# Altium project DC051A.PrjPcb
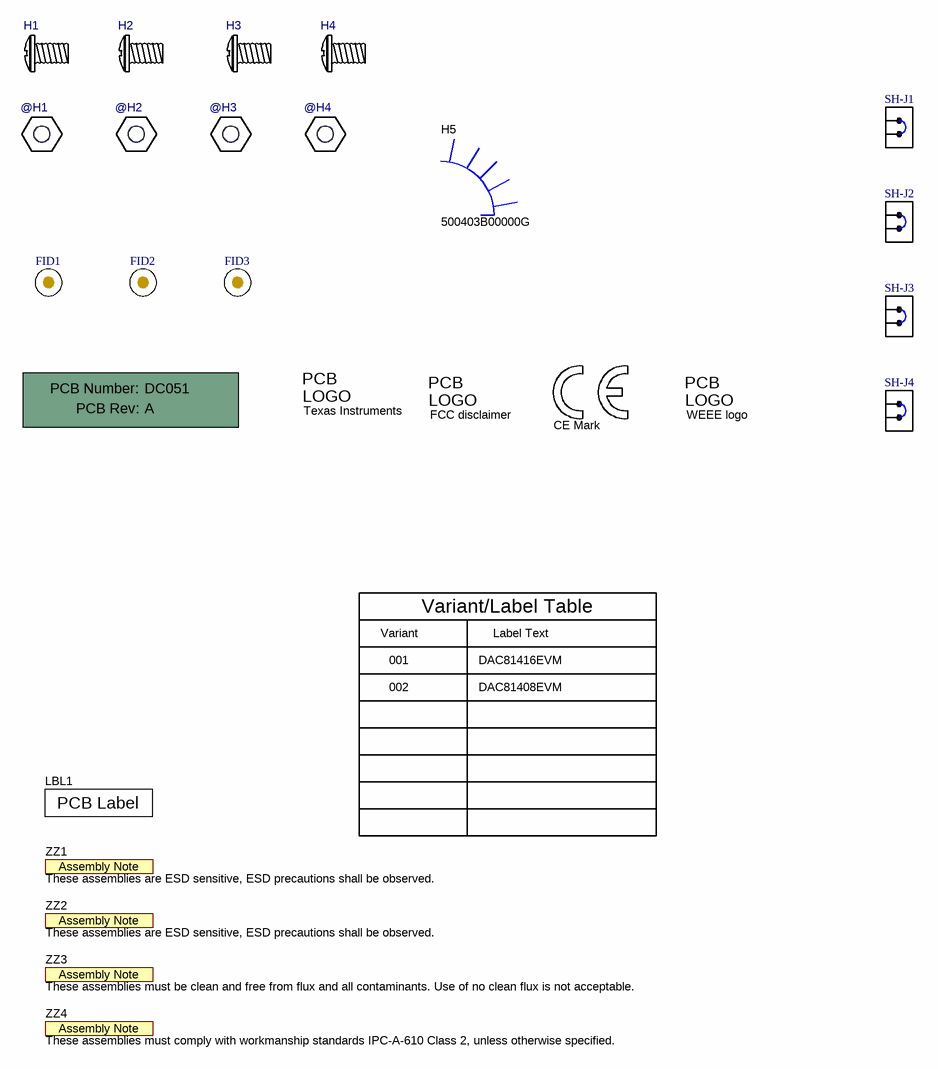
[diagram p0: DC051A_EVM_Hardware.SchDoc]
CopyrightYear: 2018; PCB_Layout: VENU; PCB_Rev: A; PRJ_Customer: Public Release; PRJ_Engineer: Uttama Kumar Sahu; PRJ_Number: DC051; PRJ_Title: DAC814xx EVM; SCH_Rev: A; TechSupport: http://www.ti.com/support; TID: N/A
2 sheets, 96 parts. Net scope: flat (ports and power ports of the same name join across sheets).
Board file: DC051A.PcbDoc
Sheets:
  DC051A_EVM_Hardware.SchDoc
  DC051A.SchDoc

## Sheet DC051A_EVM_Hardware.SchDoc
size 431 x 279 mm; Date: Not shown in title block; ApprovedBy: Not shown in title block; CheckedBy: Not shown in title block; Author: Not shown in title block; CompanyName: Not shown in title block; Engineer: Not shown in title block; Organization: Not shown in title block; Address1: Not shown in title block; Address2: Not shown in title block; Address3: Not shown in title block; Address4: Not shown in title block; DocumentNumber: 1; Revision: Use project parameter SCH_Rev; SheetNumber: 1; SheetTotal: 2; PageSetup: Record=PageOptions¦CenterHorizontal=True¦CenterVertical=True¦PrintScale=1.00¦XCorrection=1.00¦YCorrection=1.00¦PrintKind=0¦BorderSize=5000000¦LeftOffset=0¦BottomOffset=0¦Orientation=2¦PaperLength=1000¦PaperWidth=1000¦Scale=100¦PaperSource=15¦PrintQuality=600¦MediaType=1¦DitherType=10¦PaperKind=Letter¦PrintScaleMode=1

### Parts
!PCB  Printed Circuit Board  (value not drawn)  (mechanical)
@H1  1891  [Keystone_1891]  (value not drawn)
@H2  1891  [Keystone_1891]  (value not drawn)
@H3  1891  [Keystone_1891]  (value not drawn)
@H4  1891  [Keystone_1891]  (value not drawn)
FID1  Fiducial  [Fiducial10-30]  (value not drawn)
FID2  Fiducial  [Fiducial10-30]  (value not drawn)
FID3  Fiducial  [Fiducial10-30]  (value not drawn)
H1  29311  [Keystone29311]  (value not drawn)
H2  29311  [Keystone29311]  (value not drawn)
H3  29311  [Keystone29311]  (value not drawn)
H4  29311  [Keystone29311]  (value not drawn)
H5  500403B00000G  [Aavid_500403B00000G]
LBL1  THT-14-423-10  [Label_650x200]  (value not drawn)
Logo1  Texas Instruments  [TI_Stacked_Overlay_Medium]  (no BOM)
Logo2  FCC disclaimer  [FCC_disclaimer]  (no BOM)
Logo3  WEEE logo  [WEEE_Minimum]  (no BOM)
LOGO4  CE Mark  [CE_Mark_5mm]  (no BOM)
SH-J1  SNT-100-BK-G  [SNT-100-BK-G]  (value not drawn)
SH-J2  SNT-100-BK-G  [SNT-100-BK-G]  (value not drawn)
SH-J3  SNT-100-BK-G  [SNT-100-BK-G]  (value not drawn)
SH-J4  SNT-100-BK-G  [SNT-100-BK-G]  (value not drawn)
ZZ1  These assemblies are ESD sensitive, ESD precautions shall be observed.  [AssemblyNote]  (no BOM)
ZZ2  These assemblies are ESD sensitive, ESD precautions shall be observed.  [AssemblyNote]  (no BOM)
ZZ3  These assemblies must be clean and free from flux and all contaminants. Use of no clean flux is not acceptable.  [AssemblyNote]  (no BOM)
ZZ4  These assemblies must comply with workmanship standards IPC-A-610 Class 2, unless otherwise specified.  [AssemblyNote]  (no BOM)

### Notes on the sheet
- Variant
- Variant/Label Table
- Label Text
- 001
- 002
- DAC81416EVM
- DAC81408EVM

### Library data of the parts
!PCB = CMP-0003618-2: PartNumber: DC051; Manufacturer: Any
@H1-@H4 = CMP-0003792-1: Hex Standoff, #4-40, Aluminum, 1/4"; Manufacturer: Keystone
FID1-FID3 = CMP-0077181-1: Fiducial mark.  There is nothing to buy or mount.
H1-H4 = CMP-0003639-1: Screw Pan Head M3; Manufacturer: Keystone; CompType: Hardware
H5 = 500403B00000G: Square Basket Heatsink Featuring Slanted Fins; Manufacturer: Aavid; SymbolCreator: a0412235
LBL1 = CMP-0003625-1: Thermal Transfer Printable Labels, 0.650" W x 0.200" H - 10,000 per roll; Manufacturer: Brady; Note: Size: 0.65" x 0.20 "
Logo1 = CMP-0074838-1: Texas Instrument Corporate Signature; Library Reference: Logo; SymbolCreator: a0412235; Lib Reference: TI_Logo
Logo2 = CMP-0074847-1: FCC_disclaimer
Logo3 = CMP-0074769-1
LOGO4 = CMP-0074844-1: SymbolCreator: a0412235
SH-J1-SH-J4 = CMP-0003623-1: Shunt, 100mil, Gold plated, Black; Alternate PartNumber: 969102-0000-DA; Manufacturer: Samtec; Alternate Manufacturer: 3M; Value: 1x2; Note: You can "mate" this to a header by matching the designator.  i.e. use SH-J3 for header J3
ZZ1 = CMP-0003615-1: Install label in silkscreened box after final wash.  Text shall be 8 pt font.  Text shall be per the Label Table in the PDF schematic.
ZZ2-ZZ4 = CMP-0003615-1

## Sheet DC051A.SchDoc
size 431 x 279 mm; Date: Not shown in title block; ApprovedBy: Not shown in title block; CheckedBy: Not shown in title block; Author: Not shown in title block; CompanyName: Not shown in title block; Engineer: Not shown in title block; Organization: Not shown in title block; Address1: Not shown in title block; Address2: Not shown in title block; Address3: Not shown in title block; Address4: Not shown in title block; DocumentNumber: 2; Revision: Use project parameter SCH_Rev; SheetNumber: 2; SheetTotal: 2; PageSetup: Record=PageOptions¦CenterHorizontal=True¦CenterVertical=True¦PrintScale=0.62¦XCorrection=1.00¦YCorrection=1.00¦PrintKind=0¦BorderSize=5000000¦LeftOffset=0¦BottomOffset=0¦Orientation=2¦PaperLength=1000¦PaperWidth=1000¦Scale=100¦PaperSource=15¦PrintQuality=600¦MediaType=1¦DitherType=10¦PrintScaleMode=1¦PaperKind=Letter
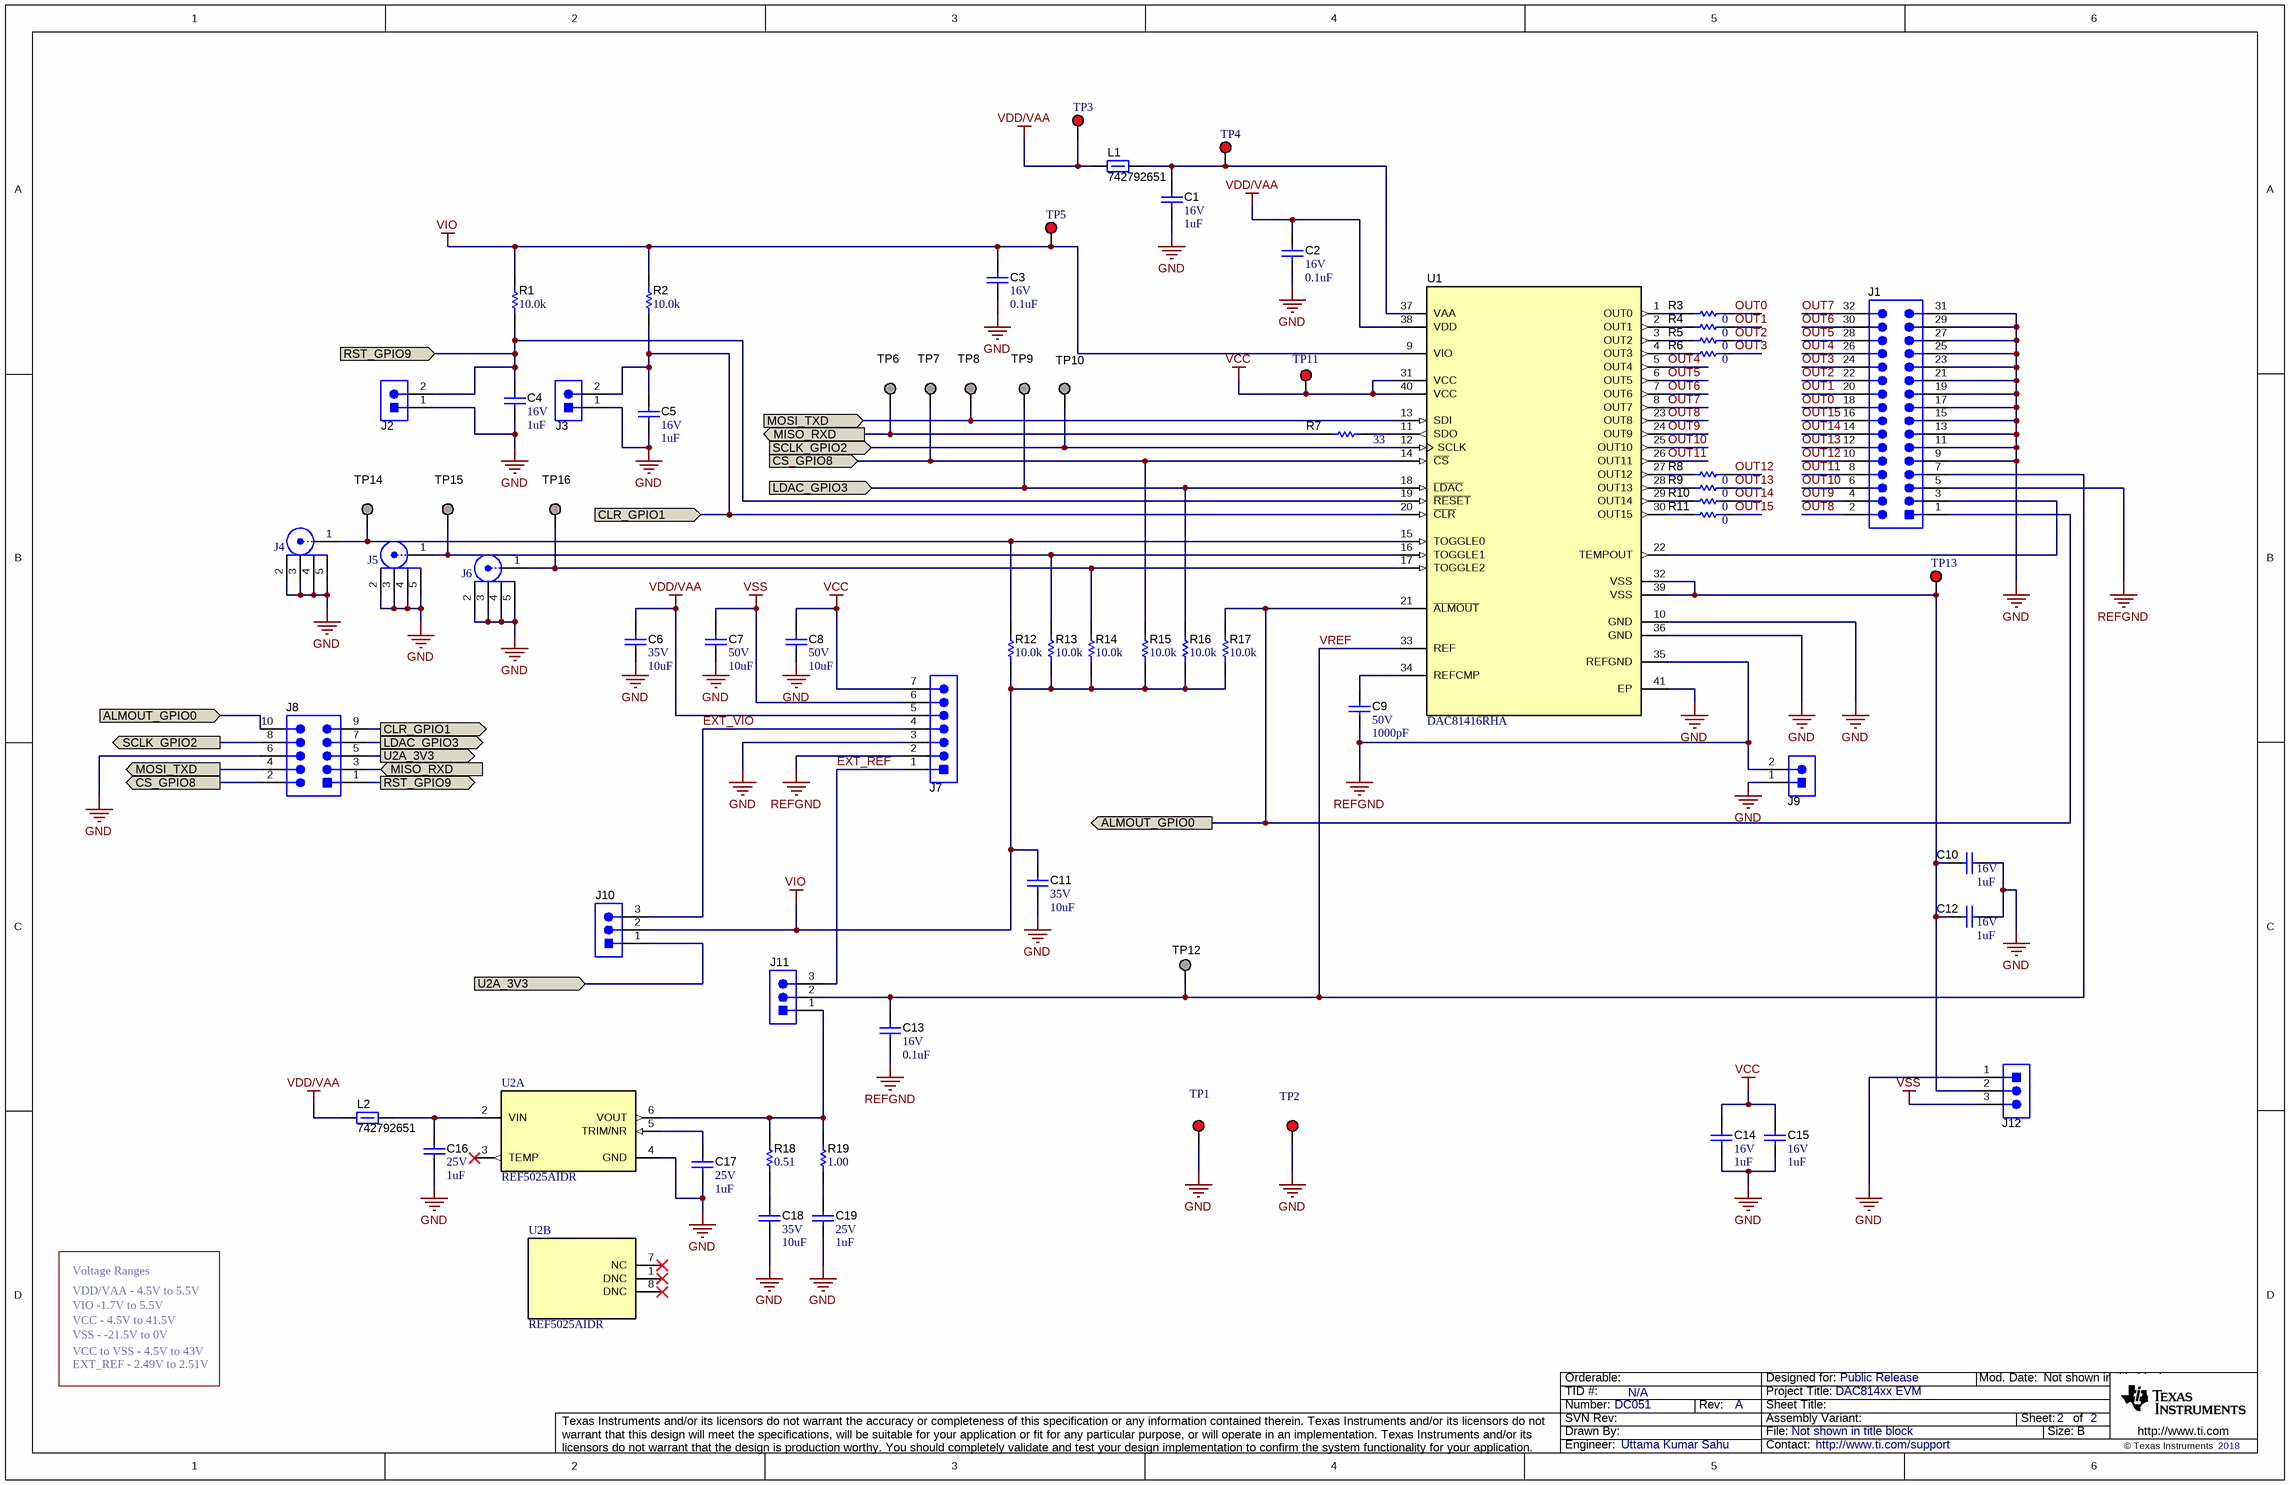
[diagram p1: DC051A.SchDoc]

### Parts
C1  VDC_V: 16V  ValueDisplayed: 1uF  [0603]  (hidden comment: C0603C105K4PACTU)
C2  VDC_V: 16V  ValueDisplayed: 0.1uF  [0603]  (hidden comment: C0603C104J4RACTU)
C3  VDC_V: 16V  ValueDisplayed: 0.1uF  [0603]  (hidden comment: C0603C104J4RACTU)
C4  VDC_V: 16V  ValueDisplayed: 1uF  [0603]  (hidden comment: C0603C105K4PACTU)
C5  VDC_V: 16V  ValueDisplayed: 1uF  [0603]  (hidden comment: C0603C105K4PACTU)
C6  VDC_V: 35V  ValueDisplayed: 10uF  [0805_HV]  (hidden comment: GRM21BC8YA106KE11L)
C7  VDC_V: 50V  ValueDisplayed: 10uF  [1210_270]  (hidden comment: UMJ325KB7106KMHT)
C8  VDC_V: 50V  ValueDisplayed: 10uF  [1210_270]  (hidden comment: UMJ325KB7106KMHT)
C9  VDC_V: 50V  ValueDisplayed: 1000pF  [0603]  (hidden comment: C0603C102K5RACTU)
C10  VDC_V: 16V  ValueDisplayed: 1uF  [0603]  (hidden comment: C0603C105K4PACTU)
C11  VDC_V: 35V  ValueDisplayed: 10uF  [0805_HV]  (hidden comment: GRM21BC8YA106KE11L)
C12  VDC_V: 16V  ValueDisplayed: 1uF  [0603]  (hidden comment: C0603C105K4PACTU)
C13  VDC_V: 16V  ValueDisplayed: 0.1uF  [0603]  (hidden comment: C0603C104J4RACTU)
C14  VDC_V: 16V  ValueDisplayed: 1uF  [0603]  (hidden comment: C0603C105K4PACTU)
C15  VDC_V: 16V  ValueDisplayed: 1uF  [0603]  (hidden comment: C0603C105K4PACTU)
C16  VDC_V: 25V  ValueDisplayed: 1uF  [0603]  (hidden comment: C1608X5R1E105K080AC)
C17  VDC_V: 25V  ValueDisplayed: 1uF  [0603]  (hidden comment: C1608X5R1E105K080AC)
C18  VDC_V: 35V  ValueDisplayed: 10uF  [0805_HV]  (hidden comment: GRM21BC8YA106KE11L)
C19  VDC_V: 25V  ValueDisplayed: 1uF  [0603]  (hidden comment: C1608X5R1E105K080AC)
J1  TSM-116-01-T-DV-P  [CONN_TSM-116-01-T-DV-P]  (value not drawn)
J2  TSM-102-01-L-SV  [Samtec_TSM-102-01-L-SV]  (value not drawn)
J3  TSM-102-01-L-SV  [Samtec_TSM-102-01-L-SV]  (value not drawn)
J4  142-0701-231  [Johnson_142-0701-231]  (value not drawn)
J5  142-0701-231  [Johnson_142-0701-231]  (value not drawn)
J6  142-0701-231  [Johnson_142-0701-231]  (value not drawn)
J7  1984662  [Phoenix_1984662]  (value not drawn)
J8  AWHW-10G-0202-T  [Assman_AWHW-10G-0x02-T]  (value not drawn)
J9  TSM-102-01-L-SV  [Samtec_TSM-102-01-L-SV]  (value not drawn)
J10  TSM-103-01-L-SV-P-TR  [Samtec_TSM-103-01-x-SV-P]  (value not drawn)
J11  TSM-103-01-L-SV-P-TR  [Samtec_TSM-103-01-x-SV-P]  (value not drawn)
J12  TSM-103-01-L-SV-P-TR  [Samtec_TSM-103-01-x-SV-P]  (value not drawn)
L1  742792651  [0603]
L2  742792651  [0603]
R1  ValueDisplayed: 10.0k  [0603]  (hidden comment: RC0603FR-0710KL)
R2  ValueDisplayed: 10.0k  [0603]  (hidden comment: RC0603FR-0710KL)
R3  ValueDisplayed: 0  [0603]  (hidden comment: RC0603JR-070RL)
R4  ValueDisplayed: 0  [0603]  (hidden comment: RC0603JR-070RL)
R5  ValueDisplayed: 0  [0603]  (hidden comment: RC0603JR-070RL)
R6  ValueDisplayed: 0  [0603]  (hidden comment: RC0603JR-070RL)
R7  ValueDisplayed: 33  [0603]  (hidden comment: CRCW060333R0JNEA)
R8  ValueDisplayed: 0  [0603]  (hidden comment: RC0603JR-070RL)
R9  ValueDisplayed: 0  [0603]  (hidden comment: RC0603JR-070RL)
R10  ValueDisplayed: 0  [0603]  (hidden comment: RC0603JR-070RL)
R11  ValueDisplayed: 0  [0603]  (hidden comment: RC0603JR-070RL)
R12  ValueDisplayed: 10.0k  [0603]  (hidden comment: RC0603FR-0710KL)
R13  ValueDisplayed: 10.0k  [0603]  (hidden comment: RC0603FR-0710KL)
R14  ValueDisplayed: 10.0k  [0603]  (hidden comment: RC0603FR-0710KL)
R15  ValueDisplayed: 10.0k  [0603]  (hidden comment: RC0603FR-0710KL)
R16  ValueDisplayed: 10.0k  [0603]  (hidden comment: RC0603FR-0710KL)
R17  ValueDisplayed: 10.0k  [0603]  (hidden comment: RC0603FR-0710KL)
R18  ValueDisplayed: 0.51  [0603]  (hidden comment: ERJ-3RQFR51V)
R19  ValueDisplayed: 1.00  [0603]  (hidden comment: RC0603FR-071RL)
TP1  5005  [Keystone5005]  (value not drawn)
TP2  5005  [Keystone5005]  (value not drawn)
TP3  5005  [Keystone5005]  (value not drawn)
TP4  5005  [Keystone5005]  (value not drawn)
TP5  5005  [Keystone5005]  (value not drawn)
TP6  5019  [Keystone_5019]  (value not drawn)
TP7  5019  [Keystone_5019]  (value not drawn)
TP8  5019  [Keystone_5019]  (value not drawn)
TP9  5019  [Keystone_5019]  (value not drawn)
TP10  5019  [Keystone_5019]  (value not drawn)
TP11  5005  [Keystone5005]  (value not drawn)
TP12  TP_SM_1MM  [TP_SM_1MM]  (value not drawn)  (no BOM)
TP13  5005  [Keystone5005]  (value not drawn)
TP14  5019  [Keystone_5019]  (value not drawn)
TP15  5019  [Keystone_5019]  (value not drawn)
TP16  5019  [Keystone_5019]  (value not drawn)
U1  DAC81416RHA  [RHA0040H]
U2  REF5025AIDR  [D0008A_N]  (parts A,B of 2)

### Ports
ALMOUT_GPIO0 (in), ALMOUT_GPIO0 (out), CLR_GPIO1 (in), CLR_GPIO1 (out), CS_GPIO8 (in), CS_GPIO8 (out), LDAC_GPIO3 (in), LDAC_GPIO3 (out), MISO_RXD (in), MISO_RXD (out), MOSI_TXD (in), MOSI_TXD (out), RST_GPIO9 (in), RST_GPIO9 (out), SCLK_GPIO2 (in), SCLK_GPIO2 (out), U2A_3V3 (in), U2A_3V3 (out)

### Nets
GND: C1.2 C2.2 C3.2 C4.2 C5.2 C6.2 C7.2 C8.2 C10.2 C11.2 C12.2 C14.2 C15.2 C16.2 C17.2 C18.2 C19.2 J1.9 J1.11 J1.13 J1.15 J1.17 J1.19 J1.21 J1.23 J1.25 J1.27 J1.29 J1.31 J2.1 J3.1 J4.2 J4.3 J4.4 J4.5 J5.2 J5.3 J5.4 J5.5 J6.2 J6.3 J6.4 J6.5 J7.3 J8.6 J9.1 J12.1 TP1.1 TP2.1 U1.10(GND) U1.36(GND) U1.41(EP) U2.4(GND)
REFGND: C9.2 C13.2 J1.5 J7.2 J9.2 U1.35(REFGND)
VCC: C8.1 C14.1 C15.1 J7.7 TP11.1 U1.31(VCC) U1.40(VCC)
VDD/VAA: C2.1 C6.1 J7.5 L1.1 L2.1 TP3.1 U1.38(VDD)
VIO: C3.1 C11.1 J10.2 R1.2 R2.2 R12.1 R13.1 R14.1 R15.1 R16.1 R17.1 TP5.1 U1.9(VIO)
VSS: C7.1 J7.6 J12.3
ALMOUT_GPIO0: J1.1 J8.10 R17.2 U1.21(~{ALMOUT}) ; port ALMOUT_GPIO0
CLR_GPIO1: C5.1 J3.2 J8.9 R2.1 U1.20(~{CLR}) ; port CLR_GPIO1
CS_GPIO8: J8.2 R15.2 TP7.1 U1.14(~{CS}) ; port CS_GPIO8
EXT_REF: J7.1 J11.3
EXT_VIO: J7.4 J10.3
LDAC_GPIO3: J8.7 R16.2 TP9.1 U1.18(~{LDAC}) ; port LDAC_GPIO3
MISO_RXD: J8.3 R7.1 TP6.1 ; port MISO_RXD
MOSI_TXD: J8.4 TP8.1 U1.13(SDI) ; port MOSI_TXD
OUT0: J1.18 R3.2
OUT1: J1.20 R4.2
OUT2: J1.22 R5.2
OUT3: J1.24 R6.2
OUT4: J1.26 U1.5(OUT4)
OUT5: J1.28 U1.6(OUT5)
OUT6: J1.30 U1.7(OUT6)
OUT7: J1.32 U1.8(OUT7)
OUT8: J1.2 U1.23(OUT8)
OUT9: J1.4 U1.24(OUT9)
OUT10: J1.6 U1.25(OUT10)
OUT11: J1.8 U1.26(OUT11)
OUT12: J1.10 R8.2
OUT13: J1.12 R9.2
OUT14: J1.14 R10.2
OUT15: J1.16 R11.2
RST_GPIO9: C4.1 J2.2 J8.1 R1.1 U1.19(~{RESET}) ; port RST_GPIO9
SCLK_GPIO2: J8.8 TP10.1 U1.12(SCLK) ; port SCLK_GPIO2
U2A_3V3: J8.5 J10.1 ; port U2A_3V3
VREF: C13.1 J1.7 J11.2 TP12.1 U1.33(REF)
NetC1_1: C1.1 L1.2 TP4.1 U1.37(VAA)
NetC9_1: C9.1 U1.34(REFCMP)
NetC10_1: C10.1 C12.1 J12.2 TP13.1 U1.32(VSS) U1.39(VSS)
NetC16_1: C16.1 L2.2 U2.2(VIN)
NetC17_1: C17.1 U2.5(TRIM/NR)
NetC18_1: C18.1 R18.1
NetC19_1: C19.1 R19.1
NetJ1_3: J1.3 U1.22(TEMPOUT)
NetJ4_1: J4.1 R12.2 TP14.1 U1.15(TOGGLE0)
NetJ5_1: J5.1 R13.2 TP15.1 U1.16(TOGGLE1)
NetJ6_1: J6.1 R14.2 TP16.1 U1.17(TOGGLE2)
NetJ11_1: J11.1 R18.2 R19.2 U2.6(VOUT)
NetR3_1: R3.1 U1.1(OUT0)
NetR4_1: R4.1 U1.2(OUT1)
NetR5_1: R5.1 U1.3(OUT2)
NetR6_1: R6.1 U1.4(OUT3)
NetR7_2: R7.2 U1.11(SDO)
NetR8_1: R8.1 U1.27(OUT12)
NetR9_1: R9.1 U1.28(OUT13)
NetR10_1: R10.1 U1.29(OUT14)
NetR11_1: R11.1 U1.30(OUT15)

Not connected (* = marked no-connect by the designer): U2 1(DNC)* 3(TEMP)* 7(NC)* 8(DNC)*

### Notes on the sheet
- Voltage Ranges
- VDD/VAA - 4.5V to 5.5V
- VIO -1.7V to 5.5V
- VCC - 4.5V to 41.5V
- VSS - -21.5V to 0V
- VCC to VSS - 4.5V to 43V
- EXT_REF - 2.49V to 2.51V

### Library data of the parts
C1 C4 C5 C10 C12 C14 C15 = CMP-0006868-5: CAP, CERM, 1 uF, 16 V, +/- 10%, X5R, 0603; Manufacturer: Kemet; TaMin_C: -55°C; Polarized: N; SizeAreaWB_mm2: 4.68; Value1: Unknown; U/M: EA; Value: 1uF; TaMax_C: 85°C; SizeZ_mm: 1; SizeX_mm: 1.6; SizeY_mm: 0.8; SizeArea_mm2: 1.28; Cap_F: 1µF; AEC Category: Q200
C2 C3 C13 = CMP-0006857-4: CAP, CERM, 0.1 uF, 16 V, +/- 5%, X7R, 0603; Manufacturer: Kemet; TaMin_C: -55°C; Polarized: N; SizeAreaWB_mm2: 4.68; Value1: Unknown; U/M: EA; Value: 0.1uF; TaMax_C: 125°C; SizeZ_mm: 1; SizeX_mm: 1.6; SizeY_mm: 0.8; SizeArea_mm2: 1.28; Cap_F: 100nF; AEC Category: Q200
C6 C11 C18 = CMP-0008273-1: CAP, CERM, 10 uF, 35 V, +/- 10%, X6S, 0805; Manufacturer: MuRata; TaMin_C: -55°C; Polarized: N; SizeAreaWB_mm2: 6.75; Value1: Unknown; U/M: EA; Value: 10uF; TaMax_C: 105°C; SizeZ_mm: 1.45; SizeX_mm: 2; SizeY_mm: 1.25; Cap_Case: 0805; SizeArea_mm2: 2.5; Cap_F: 10µF; AEC Category: Q200
C7 C8 = CMP-0009257-2: CAP, CERM, 10 uF, 50 V, +/- 10%, X7R, AEC-Q200 Grade 1, 1210; Manufacturer: Taiyo Yuden; TaMin_C: -55°C; Polarized: N; SizeAreaWB_mm2: 14.7; Value1: Unknown; U/M: EA; Value: 10uF; TaMax_C: 125°C; SizeZ_mm: 2.7; SizeX_mm: 3.2; SizeY_mm: 2.5; Cap_Case: 1210; SizeArea_mm2: 8; AEC Qualified: Y; Cap_F: 10µF; AEC Grade: 1; AEC Category: Q200
C9 = CMP-0006847-4: CAP, CERM, 1000 pF, 50 V, +/- 10%, X7R, 0603; Manufacturer: Kemet; TaMin_C: -55°C; Polarized: N; SizeAreaWB_mm2: 4.68; Value1: Unknown; U/M: EA; Value: 1000pF; TaMax_C: 125°C; SizeZ_mm: 1; SizeX_mm: 1.6; SizeY_mm: 0.8; SizeArea_mm2: 1.28; Cap_F: 1nF; AEC Category: Q200
C16 C17 C19 = CMP-0007006-5: CAP, CERM, 1 uF, 25 V, +/- 10%, X5R, 0603; Manufacturer: TDK; TaMin_C: -55°C; Polarized: N; SizeAreaWB_mm2: 4.68; Value1: Unknown; U/M: EA; Value: 1uF; TaMax_C: 85°C; SizeZ_mm: 1; SizeX_mm: 1.6; SizeY_mm: 0.8; SizeArea_mm2: 1.28; Cap_F: 1µF; AEC Category: Q200
J1 = CMP-0075449-1: Header, 100mil, 16x2, Tin, SMT; Manufacturer: Samtec; Green_REACh: Passed; CT: False; Green_Lifecycle: Active; CNHeader: True
J2 J3 J9 = CMP-0075467-1: Header, 100mil, 2x1, Gold with Tin Tail, SMT; Manufacturer: Samtec; Pitch_mm: 2.54; Gender: Male; Cert_CSA: Y; Green_REACh: Passed; Current_A: 5.4A; Voltage_V: 475V; CT: False; Shrouded: N; Green_Lifecycle: Active; Row_Count: 1; CNHeader: True
J4-J6 = CMP-0055820-1: Connector, SMA, TH; Manufacturer: Cinch Connectivity; CNHeader: FALSE; Green_Lifecycle: Not Set; Green_REACh: Incomplete; CT: TRUE
J7 = CMP-0055484-1: TERM BLOCK, 7POS, 3.5MM, TH; Manufacturer: Phoenix Contact; CNHeader: FALSE; Green_Lifecycle: Not Set; Green_REACh: Incomplete; CompType: Terminal Block; CT: TRUE
J8 = CMP-0075161-1: Header(Shrouded), 2.54mm, 5x2, Gold, TH; Manufacturer: Assman WSW; CNHeader: False; Green_Lifecycle: Active; Shrouded: Y; Gender: Male; Green_REACh: Passed; Row_Count: 2; RowSpacing_mm: 2.54
J10-J12 = CMP-0055592-1: Header, 2.54mm, 3x1, Gold, SMT; Manufacturer: Samtec; CNHeader: TRUE; Current_A: 5.4A; Shrouded: N; Gender: Male; Cert_CSA: Y; Voltage_V: 475V; Row_Count: 1; Pitch_mm: 2.54; CT: FALSE
L1 L2 = CMP-0003197-2: Ferrite Bead, 600 ohm @ 100 MHz, 1 A, 0603; Manufacturer: Wurth Elektronik; Ztyp@1GHz_Ohm: 257.548; ZTyp@100MHz_Ohm: 600; SizeAreaWB_mm2: 4.68; DCR_ohm: 2d; Value1: 0.2 ohm; Value: 600 ohm; Imax_A: 1A; SizeZ_mm: 1; SizeX_mm: 1.6; SizeY_mm: 0.8; SizeArea_mm2: 1.28
R1 R2 R12-R17 = CMP-0022746-3: RES, 10.0 k, 1%, 0.1 W, 0603; Manufacturer: Yageo America; Power_W: 100mW; TempCo: 200 ppm/C; Value_Code: 10k0; U/M: EA; Value: 10.0k; EIA_Code: E96; Res_ohm: 10k; SizeX_mm: 1.6; SizeY_mm: 0.8; SizeZ_mm: 1; Value2: 0.1W; SizeArea_mm2: 1.28; VDC_V: 150V; AEC Category: Q200
R3-R6 R8-R11 = CMP-0025885-3: RES, 0, 5%, 0.1 W, 0603; Manufacturer: Yageo America; Power_W: 100mW; TempCo: 200 ppm/C; Value_Code: 0000; U/M: EA; Value: 0; EIA_Code: E24; SizeX_mm: 1.6; SizeZ_mm: 1; Value2: 0.1W; SizeArea_mm2: 1.28; VDC_V: 50V; AEC Category: Q200; SizeY_mm: 0.8
R7 = CMP-0025787-4: RES, 33, 5%, 0.1 W, AEC-Q200 Grade 0, 0603; Manufacturer: Vishay-Dale; Power_W: 100mW; TempCo: 200 ppm/C; Value_Code: 33R0; Value: 33; EIA_Code: E24; SizeX_mm: 1.6; SizeY_mm: 0.8; SizeZ_mm: 1; Value2: 0.1W; SizeArea_mm2: 1.28; AEC Qualified: Y; VDC_V: 75V; AEC Category: Q200; AEC Grade: 0
R18 = CMP-0022717-2: RES, 0.51, 1%, 0.1 W, AEC-Q200 Grade 1, 0603; Manufacturer: Panasonic; Power_W: 100mW; TempCo: 300 ppm/C; Value_Code: R510; U/M: EA; Value: 0.51; EIA_Code: E96; Res_ohm: 5.1d; SizeX_mm: 1.6; SizeY_mm: 0.8; SizeZ_mm: 1; Value2: 0.1W; SizeArea_mm2: 1.28; AEC Qualified: Y; AEC Category: Q200
R19 = CMP-0022900-2: RES, 1.00, 1%, 0.1 W, 0603; Manufacturer: Yageo America; Power_W: 100mW; TempCo: 200 ppm/C; Value_Code: 1R00; U/M: EA; Value: 1.00; EIA_Code: E96; Res_ohm: 1; SizeX_mm: 1.6; SizeY_mm: 0.8; Value2: 0.1W; SizeArea_mm2: 1.28; VDC_V: 150V; AEC Category: Q200
TP1-TP5 TP11 TP13 = CMP-0055142-1: Test Point, Compact, Red, TH; Manufacturer: Keystone; CNHeader: FALSE; Green_Lifecycle: Active; Green_REACh: Passed; ContactFinish: Silver; CT: TRUE
TP6-TP10 TP14-TP16 = CMP-0055162-1: Test Point, Miniature, SMT; Manufacturer: Keystone; CNHeader: FALSE; Green_Lifecycle: Active; Green_REACh: Passed; CT: TRUE
TP12 = CMP-0003825-1: 1mm Test Point, SMT; Manufacturer: Any
U1 = CMP-0013795-3: 16-Channel, 16-Bit, High-Voltage Output DAC with Precision Internal Reference, RHA0040H (VQFN-40); Manufacturer: Texas Instruments; SizeX_mm: 6; CompType: IC; SizeZ_mm: 1; SizeArea_mm2: 36; SizeAreaWB_mm2: 64; U/M: EA
U2 = CMP-0032581-1: Low Noise, Very Low Drift, Precision Voltage Reference, -40 to 125 degC, 8-pin SOIC (D), Green (RoHS & no Sb/Br); Manufacturer: Texas Instruments; Iout/Iz(Max)(mA): 10; VO(V): 2.5; Temp Coeff(Max)(ppm/ degree C): 3; SubFamily: Series Voltage Reference; VI(Max)(V): 18; Iq(Max)(uA): 1000; Rating: Military; Initial Accuracy @ 25/deg C(%): 0.05; VI(Min)(V): 2.7

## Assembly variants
001: not fitted FID1 FID2 FID3 H5 J4 J5 J6
002: not fitted FID1 FID2 FID3 H5 J4 J5 J6 R3 R4 R5 R6 R8 R9 R10 R11 TP14 TP15 TP16; alternate parts U1 -> CMP-0080513-1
